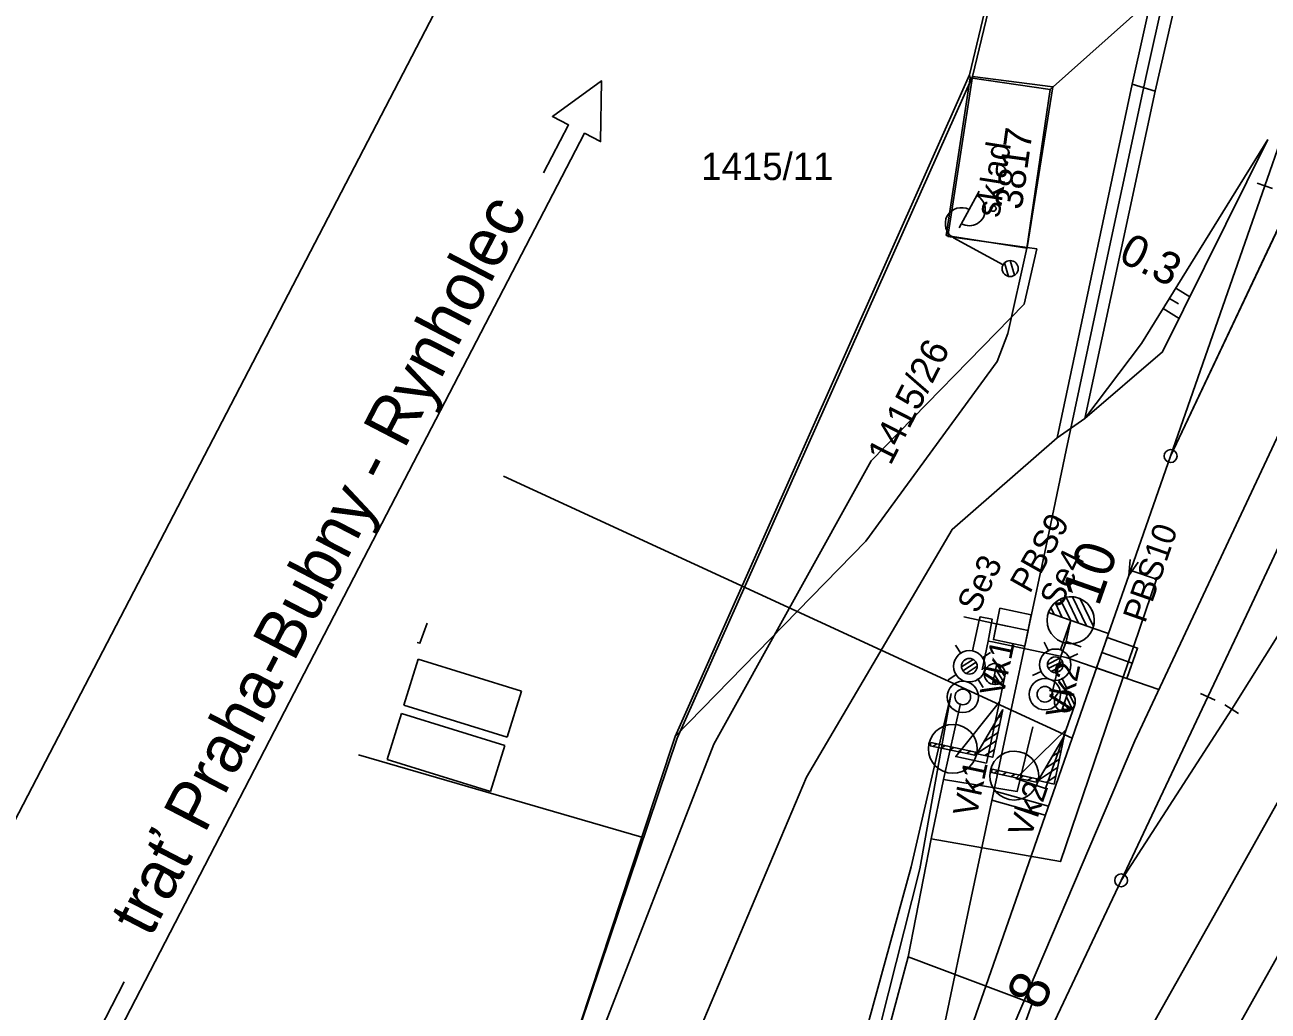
# Model space of a CAD drawing. Extents: x -781083 to -763634, y -1029516 to -1022695.
# Drawn here: x -765251.4 to -765174.1, y -1024213.6 to -1024152.2 of the extents above; entities that cross this region are included whole.
import ezdxf

# ---------------------------------------------------------------- set-up
doc = ezdxf.new("R2010")
doc.units = 0
for name, color, linetype in [('Default', 7, 'Continuous'), ('Hranice parcel', 7, 'Continuous'), ('Parcelní čísla', 7, 'Continuous'), ('PS_12-01-10_Kabelizace_nove_kabelizace', 7, 'Continuous'), ('PS_12-01-11_SZZ_Slany_nove_prvky', 7, 'Continuous'), ('PS_12-01-11_SZZ_Slany_nove_prvky_popis', 7, 'Continuous'), ('směry', 7, 'Continuous'), ('Vnitřní kresba', 7, 'Continuous'), ('Vrstva 1', 7, 'Continuous'), ('Vrstva 16', 7, 'Continuous'), ('Vrstva 17', 7, 'Continuous'), ('Vrstva 2', 7, 'Continuous'), ('Vrstva 23', 7, 'Continuous'), ('Vrstva 25', 7, 'Continuous'), ('Vrstva 28', 7, 'Continuous'), ('Vrstva 3', 7, 'Continuous'), ('Vrstva 4', 7, 'Continuous'), ('Vrstva 48', 7, 'Continuous'), ('Vrstva 49', 7, 'Continuous'), ('Vrstva 51', 7, 'Continuous'), ('Vrstva 7', 7, 'Continuous'), ('Značky budov', 7, 'Continuous')]:
    doc.layers.add(name, color=color, linetype=linetype)

# ---------------------------------------------------------------- blocks, each defined once
blk = doc.blocks.new('4.02')
at = {"layer": 'Značky budov'}
blk.add_circle((-0.07, 0.01), 1.75, dxfattribs=at)
blk = doc.blocks.new('C669_18')
at = {"layer": 'Vrstva 25'}
for p, q in [((0, 5), (0, 40.01)), ((7, 40), (32.99, 40)), ((-4.78, -1.46), (1.45, 4.76)), ((-2.4, -4.37), (4.38, 2.4))]:
    blk.add_line(p, q, dxfattribs=at)
blk.add_circle((0, 0), 5, dxfattribs=at)
blk.add_circle((0, 0), 5, dxfattribs=at)
for centre, start, end in [((10, 40), 0.00019, 180.00019), ((20, 39.88), 179.29762, 0.70276)]:
    blk.add_arc(centre, 10, start, end, dxfattribs=at)
blk = doc.blocks.new('C084_2')
at = {"layer": 'Vrstva 2'}
blk.add_line((0, 5), (0, -5), dxfattribs=at)
blk = doc.blocks.new('C321')
at = {"layer": 'Vrstva 2'}
blk.add_lwpolyline([(9.66, 2.59), (0, 0), (9.66, -2.59)], dxfattribs=at)
blk = doc.blocks.new('C083_1')
at = {"layer": 'Vrstva 2'}
blk.add_circle((0, 0), 4, dxfattribs=at)
blk = doc.blocks.new('C515_6')
at = {"layer": 'Vrstva 2'}
for p, q in [((-0.02, 35.76), (3.35, 39.13)), ((-0.03, 19.84), (12.53, 32.4)), ((-0.02, 30.45), (7.16, 37.63)), ((-0.02, 25.15), (10.19, 35.36)), ((-0.03, 14.54), (14.1, 28.67)), ((1.1, 10.37), (14.53, 23.79)), ((0, 10.29), (0, 0))]:
    blk.add_line(p, q, dxfattribs=at)
blk.add_lwpolyline([(0, 39.56), (0, 10.29)], dxfattribs=at)
blk.add_circle((0, 24.93), 14.64, dxfattribs=at)
blk.add_arc((0, 24.93), 14.63, 270.01913, 89.97998, dxfattribs=at)
blk = doc.blocks.new('POINT_DISPLAY')
at = {"layer": 'Default'}
blk.add_line((0, 0), (0, 0), dxfattribs=at)
blk = doc.blocks.new('C335')
at = {"layer": 'Vrstva 7'}
blk.add_blockref('POINT_DISPLAY', (0, 0), dxfattribs=at)
blk = doc.blocks.new('C676')
at = {"layer": 'Vrstva 3'}
for p, q in [((-29.34, 40.74), (-31.42, 42.8)), ((-29.34, 35.42), (-31.42, 37.4)), ((-29.34, 30.02), (-31.42, 32.1)), ((-29.34, 24.62), (-31.42, 26.7)), ((-29.34, 19.22), (-31.42, 21.38)), ((-25.29, 5), (-30.34, 10.04)), ((-19.89, 5), (-29.97, 15.09)), ((-14.58, 5), (-21.78, 12.3)), ((-9.28, 5), (-13.67, 9.58)), ((-3.88, 5), (-5.69, 6.91))]:
    blk.add_line(p, q, dxfattribs=at)
for points in [[(-29.34, 44.52), (-31.42, 44.52), (-31.42, 16.17), (-29.34, 16.17)], [(0, 5), (-30.34, 5), (-30.34, 15.17)]]:
    blk.add_lwpolyline(points, close=True, dxfattribs=at)
blk.add_ellipse((-30.36, 30.35), major_axis=(0, -15.19), ratio=0.999996, dxfattribs=at)
blk = doc.blocks.new('C676_1')
at = {"layer": 'Vrstva 3'}
for p, q in [((-29.34, 40.74), (-31.42, 42.8)), ((-29.34, 35.42), (-31.42, 37.4)), ((-29.34, 30.02), (-31.42, 32.1)), ((-29.34, 24.62), (-31.42, 26.7)), ((-29.34, 19.22), (-31.42, 21.38)), ((-25.29, 5), (-30.34, 10.04)), ((-19.89, 5), (-29.97, 15.09)), ((-14.58, 5), (-21.78, 12.3)), ((-9.28, 5), (-13.67, 9.58)), ((-3.88, 5), (-5.69, 6.91))]:
    blk.add_line(p, q, dxfattribs=at)
for points in [[(-29.34, 44.52), (-31.42, 44.52), (-31.42, 16.17), (-29.34, 16.17)], [(0, 5), (-30.34, 5), (-30.34, 15.17)]]:
    blk.add_lwpolyline(points, close=True, dxfattribs=at)
blk.add_ellipse((-30.36, 30.35), major_axis=(0, -15.19), ratio=0.999996, dxfattribs=at)
blk = doc.blocks.new('NS5_1')
at = {"layer": 'PS_12-01-11_SZZ_Slany_nove_prvky'}
for p, q in [((-10, 55), (-17, 62)), ((10, 55), (17, 62)), ((-7.3, 43.4), (1.6, 52.3)), ((-5.5, 39.9), (5.1, 50.5)), ((-2.2, 37.8), (7.1, 47.2)), ((3.8, 38.5), (6.4, 41.2)), ((-10, 35), (-17, 28)), ((0, 30), (0, 0)), ((10, 35), (17, 28)), ((-15, 0), (15, 0))]:
    blk.add_line(p, q, dxfattribs=at)
for centre, radius in [((0, 75), 15), ((0, 75), 7.5), ((0, 45), 15), ((0, 45), 7.5)]:
    blk.add_circle(centre, radius, dxfattribs=at)
blk = doc.blocks.new('NS5')
at = {"layer": 'PS_12-01-11_SZZ_Slany_nove_prvky'}
for p, q in [((-10, 55), (-17, 62)), ((10, 55), (17, 62)), ((-7.3, 43.4), (1.6, 52.3)), ((-5.5, 39.9), (5.1, 50.5)), ((-2.2, 37.8), (7.1, 47.2)), ((3.8, 38.5), (6.4, 41.2)), ((-10, 35), (-17, 28)), ((0, 30), (0, 0)), ((10, 35), (17, 28)), ((-15, 0), (15, 0))]:
    blk.add_line(p, q, dxfattribs=at)
for centre, radius in [((0, 75), 15), ((0, 75), 7.5), ((0, 45), 15), ((0, 45), 7.5)]:
    blk.add_circle(centre, radius, dxfattribs=at)
blk = doc.blocks.new('VU26')
at = {"layer": 'PS_12-01-11_SZZ_Slany_nove_prvky'}
for p, q in [((-95, 20), (-75, 20)), ((-84.8, 10), (-94.8, 20)), ((-80.5, 11.1), (-89.5, 20)), ((-77.5, 13.4), (-84.2, 20)), ((-75.6, 16.7), (-78.8, 20)), ((-60, 10), (-85, 10))]:
    blk.add_line(p, q, dxfattribs=at)
blk.add_lwpolyline([(0, 10), (-60, 10), (0, 40)], close=True, dxfattribs=at)
blk.add_lwpolyline([(-95, 20), (-75, 20)], dxfattribs=at)
blk.add_circle((-85, 20), 10, dxfattribs=at)
blk.add_arc((-85, 20), 10, 179.9962, 0.0016, dxfattribs=at)
blk.add_arc((-85, 20), 10, 179.9962, 0.0016, dxfattribs=at)
blk = doc.blocks.new('VU26_1')
at = {"layer": 'PS_12-01-11_SZZ_Slany_nove_prvky'}
for p, q in [((-95, 20), (-75, 20)), ((-84.8, 10), (-94.7, 20)), ((-80.5, 11.1), (-89.5, 20)), ((-77.5, 13.4), (-84.2, 20)), ((-75.6, 16.7), (-78.8, 20)), ((-60, 10), (-85, 10))]:
    blk.add_line(p, q, dxfattribs=at)
blk.add_lwpolyline([(0, 10), (-60, 10), (0, 40)], close=True, dxfattribs=at)
blk.add_lwpolyline([(-95, 20), (-75, 20)], dxfattribs=at)
blk.add_circle((-85, 20), 10, dxfattribs=at)
blk.add_arc((-85, 20), 10, 179.9962, 0.0016, dxfattribs=at)
blk.add_arc((-85, 20), 10, 179.9962, 0.0016, dxfattribs=at)
blk = doc.blocks.new('SB113')
at = {"layer": 'PS_12-01-11_SZZ_Slany_nove_prvky'}
for points in [[(-20.3, -97.7), (20.3, 97.7), (-174.8, 139.2), (-215.5, -56.1)], [(0, 0), (-20.3, -97.7), (-215.5, -56.1), (-195.1, 41.5)]]:
    blk.add_lwpolyline(points, close=True, dxfattribs=at)
blk = doc.blocks.new('SB113_1')
at = {"layer": 'PS_12-01-11_SZZ_Slany_nove_prvky'}
for points in [[(-33.2, -94.3), (33.2, 94.3), (221.9, 27.9), (155.4, -160.7)], [(0, 0), (-33.2, -94.3), (155.4, -160.7), (188.7, -66.4)]]:
    blk.add_lwpolyline(points, close=True, dxfattribs=at)

msp = doc.modelspace()

# ---------------------------------------------------------------- linework, layer by layer
msp.add_lwpolyline([(-765336.117, -1024363.479), (-765204.05, -1024432.093), (-764769.725, -1023596.107), (-764901.792, -1023527.494)], close=True)
at = {"layer": 'Hranice parcel'}
for p, q in [((-765192.7, -1024155.34), (-765187.08, -1024131.97)), ((-765211, -1024196.48), (-765192.7, -1024155.34)), ((-765192.7, -1024155.34), (-765192.66, -1024155.52)), ((-765187.69, -1024156.25), (-765192.66, -1024155.52)), ((-765187.69, -1024156.25), (-765189.13, -1024166.12)), ((-765211, -1024196.48), (-765213.08, -1024202.74)), ((-765230.685, -1024197.628), (-765213.08, -1024202.74))]:
    msp.add_line(p, q, dxfattribs=at)
for points in [[(-765116.35, -1024047.19), (-765153.59, -1024112.04), (-765161.39, -1024109.58), (-765173.08, -1024143.22), (-765187.69, -1024156.25)], [(-765192.66, -1024155.52), (-765194.15, -1024165.33), (-765189.13, -1024166.12)], [(-765189.13, -1024166.12), (-765190.32, -1024171.43), (-765190.98, -1024173.16), (-765199.15, -1024184.35), (-765211, -1024196.48)], [(-765226.433, -1024189.444), (-765226.87, -1024190.69), (-765227.051, -1024190.634)], [(-765213.08, -1024202.74), (-765218.18, -1024218.22), (-765219.59, -1024222.39), (-765251.79, -1024317.45)]]:
    msp.add_lwpolyline(points, dxfattribs=at)
at = {"layer": 'PS_12-01-10_Kabelizace_nove_kabelizace'}
for p, q in [((-765191.339, -1024189.423), (-765190.361, -1024189.632)), ((-765191.548, -1024190.556), (-765191.921, -1024192.339)), ((-765186.698, -1024190.58), (-765185.754, -1024190.91)), ((-765187.02, -1024191.502), (-765187.615, -1024194.022))]:
    msp.add_line(p, q, dxfattribs=at)
for points in [[(-765187.778, -1024240.091), (-765178.835, -1024224.275), (-765179.085, -1024224.133), (-765182.574, -1024222.177), (-765183.179, -1024221.837), (-765186.668, -1024219.881), (-765187.68, -1024219.499), (-765191.287, -1024217.769), (-765191.359, -1024217.739), (-765182.417, -1024196.766), (-765166.811, -1024163.482)], [(-765191.548, -1024190.556), (-765191.295, -1024189.186), (-765192.047, -1024189.053), (-765192.102, -1024189.26)], [(-765187.02, -1024191.502), (-765186.698, -1024190.58), (-765186.409, -1024189.26)], [(-765180.92, -1024193.571), (-765182.911, -1024192.874), (-765186.692, -1024191.568), (-765187.349, -1024191.436), (-765191.262, -1024190.609), (-765191.548, -1024190.556)]]:
    msp.add_lwpolyline(points, dxfattribs=at)
at = {"layer": 'směry'}
for points in [[(-765230.359, -1024185.393), (-765216.638, -1024158.97), (-765215.641, -1024159.488), (-765215.583, -1024155.721), (-765218.632, -1024157.935), (-765217.635, -1024158.452), (-765219.188, -1024161.443)], [(-765230.359, -1024185.393), (-765245.808, -1024215.246), (-765244.81, -1024215.762), (-765247.855, -1024217.981), (-765247.803, -1024214.214), (-765246.805, -1024214.73), (-765245.257, -1024211.737)]]:
    msp.add_lwpolyline(points, dxfattribs=at)
at = {"layer": 'Vnitřní kresba'}
for p, q in [((-765227.87, -1024194.55), (-765226.98, -1024191.68)), ((-765226.98, -1024191.68), (-765220.56, -1024193.67)), ((-765220.56, -1024193.67), (-765221.45, -1024196.54)), ((-765221.45, -1024196.54), (-765227.87, -1024194.55)), ((-765228.91, -1024197.91), (-765228.02, -1024195.05)), ((-765228.02, -1024195.05), (-765221.6, -1024197.04)), ((-765221.6, -1024197.04), (-765222.49, -1024199.9)), ((-765222.49, -1024199.9), (-765228.91, -1024197.91))]:
    msp.add_line(p, q, dxfattribs=at)
at = {"layer": 'Vrstva 1'}
for points in [[(-765188.123, -1024215.705), (-765183.275, -1024205.436), (-765176.4, -1024194.792), (-765173.261, -1024189.785), (-765169.195, -1024182.942), (-765164.586, -1024174.885), (-765158.873, -1024164.755), (-765150.27, -1024149.435), (-765143.977, -1024138.227), (-765137.411, -1024126.534), (-765129.538, -1024112.519), (-765123.879, -1024102.438), (-765115.14, -1024086.868), (-765106.342, -1024071.201), (-765098.535, -1024057.295), (-765090.39, -1024042.796), (-765081.493, -1024026.948), (-765072.655, -1024011.193), (-765066.823, -1024000.8), (-765059.521, -1023987.798)], [(-765188.645, -1024216.807), (-765188.123, -1024215.705), (-765183.275, -1024205.436), (-765177.884, -1024194.018), (-765175.294, -1024188.539), (-765171.011, -1024179.395), (-765166.902, -1024170.85), (-765161.865, -1024161.015), (-765157.64, -1024153.172), (-765153.216, -1024145.159), (-765145.723, -1024131.826), (-765138.513, -1024118.992), (-765134.338, -1024111.53), (-765125.127, -1024095.069), (-765118.846, -1024083.871), (-765111.182, -1024070.221), (-765102.382, -1024054.5), (-765092.788, -1024037.408), (-765084.151, -1024022.024), (-765076.991, -1024009.249), (-765068.63, -1023994.356)], [(-765184.058, -1024190.088), (-765182.786, -1024186.475), (-765180.198, -1024179.051), (-765174.335, -1024162.235), (-765173.249, -1024159.096), (-765170.589, -1024151.445), (-765166.869, -1024140.761), (-765164.481, -1024133.909), (-765161.079, -1024124.115)], [(-765215.522, -1024287.533), (-765214.869, -1024286.147), (-765208.592, -1024272.488), (-765202.041, -1024257.278), (-765199.225, -1024250.55), (-765195.719, -1024242.277), (-765191.973, -1024234.063), (-765191.905, -1024233.922), (-765187.773, -1024225.954), (-765183.261, -1024217.887), (-765177.292, -1024207.279), (-765170.878, -1024195.834), (-765163.532, -1024182.764), (-765155.727, -1024168.863), (-765148.415, -1024155.812), (-765140.866, -1024142.346)], [(-765200.909, -1024238.522), (-765200.512, -1024237.363), (-765196.775, -1024226.639), (-765194.217, -1024214.221), (-765192.75, -1024207.206), (-765190.136, -1024194.92), (-765187.944, -1024184.628), (-765186.685, -1024178.691), (-765184.006, -1024166.028), (-765181.702, -1024155.329), (-765179.632, -1024145.998)], [(-765208.592, -1024272.488), (-765200.394, -1024258.001), (-765194.324, -1024247.14), (-765187.882, -1024235.72), (-765182.524, -1024226.176), (-765175.117, -1024212.969), (-765167.745, -1024199.837), (-765160.378, -1024186.68), (-765154.91, -1024176.911), (-765146.757, -1024162.404), (-765139.177, -1024148.91)], [(-765184.058, -1024190.088), (-765182.786, -1024186.475), (-765180.198, -1024179.051), (-765172.246, -1024162.211)], [(-765192.593, -1024214.636), (-765189.514, -1024205.768), (-765186.319, -1024196.582), (-765184.058, -1024190.088)]]:
    msp.add_lwpolyline(points, dxfattribs=at)
at = {"layer": 'Vrstva 16'}
for points in [[(-765181.15, -1024156.349), (-765182.597, -1024155.921), (-765178.308, -1024136.757), (-765173.691, -1024118.058), (-765167.981, -1024094.617)], [(-765181.15, -1024156.349), (-765176.761, -1024137.212), (-765172.358, -1024119.206), (-765166.513, -1024095.33)]]:
    msp.add_lwpolyline(points, dxfattribs=at)
at = {"layer": 'Vrstva 17'}
msp.add_lwpolyline([(-765247.548, -1024305.21), (-765228.844, -1024249.881), (-765210.873, -1024196.594), (-765192.521, -1024155.45), (-765183.275, -1024117.083), (-765178.507, -1024097.058)], dxfattribs=at)
at = {"layer": 'Vrstva 2'}
for p, q in [((-765180.198, -1024179.051), (-765172.246, -1024162.211)), ((-765183.275, -1024205.436), (-765176.4, -1024194.792))]:
    msp.add_line(p, q, dxfattribs=at)
for points in [[(-765184.058, -1024190.088), (-765182.786, -1024186.475), (-765180.198, -1024179.051), (-765174.335, -1024162.235)], [(-765188.645, -1024216.807), (-765188.123, -1024215.705), (-765183.275, -1024205.436), (-765177.884, -1024194.018)]]:
    msp.add_lwpolyline(points, dxfattribs=at)
at = {"layer": 'Vrstva 23'}
msp.add_lwpolyline([(-765187.514, -1024156.085), (-765192.521, -1024155.45), (-765194.044, -1024165.392), (-765189.107, -1024166.085), (-765187.514, -1024156.085)], dxfattribs=at)
at = {"layer": 'Vrstva 28'}
msp.add_line((-765182.66, -1024186.156), (-765181.069, -1024186.697), dxfattribs=at)
for points in [[(-765195.082, -1024202.849), (-765187.044, -1024204.272), (-765181.069, -1024186.697)], [(-765194.327, -1024199.16), (-765193.269, -1024194.444)], [(-765194.327, -1024199.16), (-765189.737, -1024199.907), (-765188.757, -1024195.88)], [(-765196.522, -1024210.191), (-765195.082, -1024202.849), (-765194.327, -1024199.16)], [(-765204.008, -1024235.573), (-765201.849, -1024230.046), (-765196.522, -1024210.191), (-765188.801, -1024213.093), (-765189.354, -1024214.586)]]:
    msp.add_lwpolyline(points, dxfattribs=at)
at = {"layer": 'Vrstva 3'}
msp.add_line((-765186.319, -1024196.582), (-765221.68, -1024180.297), dxfattribs=at)
at = {"layer": 'Vrstva 4'}
msp.add_lwpolyline([(-765187.257, -1024177.919), (-765185.532, -1024176.714), (-765181.15, -1024156.349), (-765182.597, -1024155.921), (-765187.257, -1024177.919)], dxfattribs=at)
at = {"layer": 'Vrstva 48'}
for p, q in [((-765178.998, -1024169.142), (-765179.865, -1024168.605)), ((-765179.703, -1024169.587), (-765180.26, -1024169.242)), ((-765179.667, -1024170.491), (-765180.654, -1024169.88))]:
    msp.add_line(p, q, dxfattribs=at)
at = {"layer": 'Vrstva 49'}
for points in [[(-765185.532, -1024176.714), (-765180.7, -1024172.574), (-765174.145, -1024159.358)], [(-765185.532, -1024176.714), (-765181.998, -1024172.052), (-765174.145, -1024159.358)], [(-765224.162, -1024291.367), (-765215.697, -1024267.565), (-765204.627, -1024236.377), (-765202.143, -1024229.903), (-765195.789, -1024204.722), (-765193.85, -1024193.807)], [(-765203.195, -1024229.565), (-765196.324, -1024204.593), (-765193.85, -1024193.807)]]:
    msp.add_lwpolyline(points, dxfattribs=at)
at = {"layer": 'Vrstva 51'}
for points in [[(-765189.293, -1024169.604), (-765188.513, -1024166.16)], [(-765188.513, -1024166.16), (-765189.107, -1024166.085)], [(-765227.767, -1024250.123), (-765216.209, -1024216.525), (-765208.606, -1024196.975), (-765198.808, -1024179.343), (-765189.293, -1024169.604)], [(-765222.558, -1024251.694), (-765211.04, -1024218.422), (-765202.83, -1024199.018), (-765193.772, -1024183.61), (-765187.257, -1024177.919)]]:
    msp.add_lwpolyline(points, dxfattribs=at)
at = {"layer": 'Vrstva 7'}
for p, q in [((-765187.791, -1024200.814), (-765191.188, -1024199.865)), ((-765187.988, -1024201.381), (-765191.313, -1024200.453))]:
    msp.add_line(p, q, dxfattribs=at)

# ---------------------------------------------------------------- block references
at = {"layer": 'PS_12-01-11_SZZ_Slany_nove_prvky'}
for name, p, xscale, yscale in [('SB113', (-765189.063, -1024189.903), 0.01, 0.01), ('SB113_1', (-765184.47, -1024191.27), 0.010000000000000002, 0.010000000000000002)]:
    msp.add_blockref(name, p, dxfattribs=dict(at, xscale=xscale, yscale=yscale))
for name, p, xscale, yscale, rotation in [('NS5', (-765192.102, -1024189.26), 0.06499999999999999, 0.06499999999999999, 167.9767371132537), ('NS5_1', (-765186.409, -1024189.26), 0.065, 0.06500000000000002, 160.80354148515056), ('VU26', (-765191.01, -1024198.282), 0.06499999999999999, -0.065, -102.0112885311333), ('VU26_1', (-765187.361, -1024199.946), 0.06499999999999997, -0.06499999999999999, -109.1782822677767)]:
    msp.add_blockref(name, p, dxfattribs=dict(at, xscale=xscale, yscale=yscale, rotation=rotation))
at = {"layer": 'Vrstva 2'}
for name, p, xscale, yscale, rotation in [('C084_2', (-765174.335, -1024162.235), 0.1, 0.09999999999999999, 70.77947250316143), ('C083_1', (-765180.198, -1024179.051), 0.09999999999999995, 0.09999999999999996, -109.22052751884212), ('C321', (-765182.786, -1024186.475), 0.09999999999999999, 0.09999999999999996, 70.77947250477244), ('C515_6', (-765184.058, -1024190.088), 0.09999999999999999, 0.09999999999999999, 70.60477092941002), ('C084_2', (-765177.884, -1024194.018), 0.1, 0.09999999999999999, 64.72677839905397), ('C084_2', (-765176.4, -1024194.792), 0.09999999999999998, 0.09999999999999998, 57.14241372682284), ('C083_1', (-765183.275, -1024205.436), 0.09999999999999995, 0.09999999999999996, -115.27322160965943)]:
    msp.add_blockref(name, p, dxfattribs=dict(at, xscale=xscale, yscale=yscale, rotation=rotation))
at = {"layer": 'Vrstva 25', "xscale": 0.09999999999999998, "yscale": 0.09999999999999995, "rotation": 61.44251277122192}
msp.add_blockref('C669_18', (-765190.172, -1024167.388), dxfattribs=at)
at = {"layer": 'Vrstva 3'}
for name, p, xscale, yscale, rotation in [('C676', (-765190.136, -1024194.92), 0.1, 0.10000000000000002, 77.98871147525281), ('C676_1', (-765186.319, -1024196.582), 0.09999999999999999, 0.09999999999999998, 77.97673711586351)]:
    msp.add_blockref(name, p, dxfattribs=dict(at, xscale=xscale, yscale=yscale, rotation=rotation))
at = {"layer": 'Vrstva 7', "xscale": 0.10000000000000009, "yscale": 0.10000000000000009, "rotation": 90}
msp.add_blockref('C335', (-765189.615, -1024200.616), dxfattribs=at)
at = {"layer": 'Značky budov', "xscale": 0.1, "yscale": 0.10000000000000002}
msp.add_blockref('4.02', (-765191.22, -1024163.65), dxfattribs=at)

# ---------------------------------------------------------------- texts
at = {"layer": 'Parcelní čísla'}
for s, rotation, p in [('3817', 82, (-765189.462, -1024163.781)), ('1415/26', 63, (-765197.616, -1024179.691))]:
    msp.add_text(s, height=1.7, rotation=rotation, dxfattribs=at).set_placement(p)
msp.add_text('1415/11', height=1.7, dxfattribs=at).set_placement((-765209.38, -1024161.88))
at = {"layer": 'PS_12-01-11_SZZ_Slany_nove_prvky_popis'}
for s, rotation, p in [('PBS9', 60.60625, (-765188.956, -1024187.651)), ('PBS10', 70.80354, (-765181.787, -1024189.496)), ('Se3', 63.99951, (-765192.191, -1024188.91)), ('Se4', 63.99951, (-765187.052, -1024188.558)), ('Vk1', 77.98871, (-765192.275, -1024201.557)), ('Vk2', 70.82172, (-765188.919, -1024202.873))]:
    msp.add_text(s, height=1.5, rotation=rotation, dxfattribs=at).set_placement(p)
at = {"layer": 'směry'}
msp.add_text('trať Praha-Bubny - Rynholec', height=2.9952, rotation=62.55167, dxfattribs=at).set_placement((-765243.627, -1024209.055))
at = {"layer": 'Vrstva 2'}
for s, rotation, p in [('10', 70.60477, (-765184.676, -1024188.466)), ('8', 64.65382, (-765188.236, -1024213.623))]:
    msp.add_text(s, height=2.5, rotation=rotation, dxfattribs=at).set_placement(p)
at = {"layer": 'Vrstva 23'}
msp.add_text('sklad', height=1.5, rotation=80.94883, dxfattribs=at).set_placement((-765190.853, -1024164.259))
at = {"layer": 'Vrstva 3'}
for s, rotation, p in [('Vk1', 77.98871, (-765190.607, -1024194.072)), ('Vk2', 77.97674, (-765186.514, -1024195.437))]:
    msp.add_text(s, height=1.5, rotation=rotation, dxfattribs=at).set_placement(p)
at = {"layer": 'Vrstva 48'}
msp.add_text('0.3', height=2, rotation=333.46045, dxfattribs=at).set_placement((-765183.52, -1024166.891))

doc.saveas('drawing.dxf')
